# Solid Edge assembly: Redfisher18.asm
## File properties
Author: m_hel
Template: iso metric assembly.asm
Last saved by: m_hel
Revision: 75
Application: Solid Edge
Username: m_hel
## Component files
Tube.par
Smaller Nut.par
Rigging Box.par
Deck1.par
Hull.par
Deck Base.par
Propeller.par
Aft Storage Lid.asm
Center Console.asm
Aft Storage.par
Big bolt.par
Front Storage Lid.asm
Back Rails.par
Rigging Box Lid.asm
Livewell Lid.asm
Cup Holder.psm
Handlebar.par
Livewell.par
Back well.par
Smaller Bolt.par
Even Bigger Bolt.par
Casting Deck.par
Attachment.par
Attachment2.par
Enginev2.par
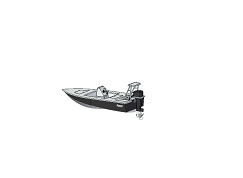
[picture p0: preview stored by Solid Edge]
